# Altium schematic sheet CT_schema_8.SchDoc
size 277 x 170 mm
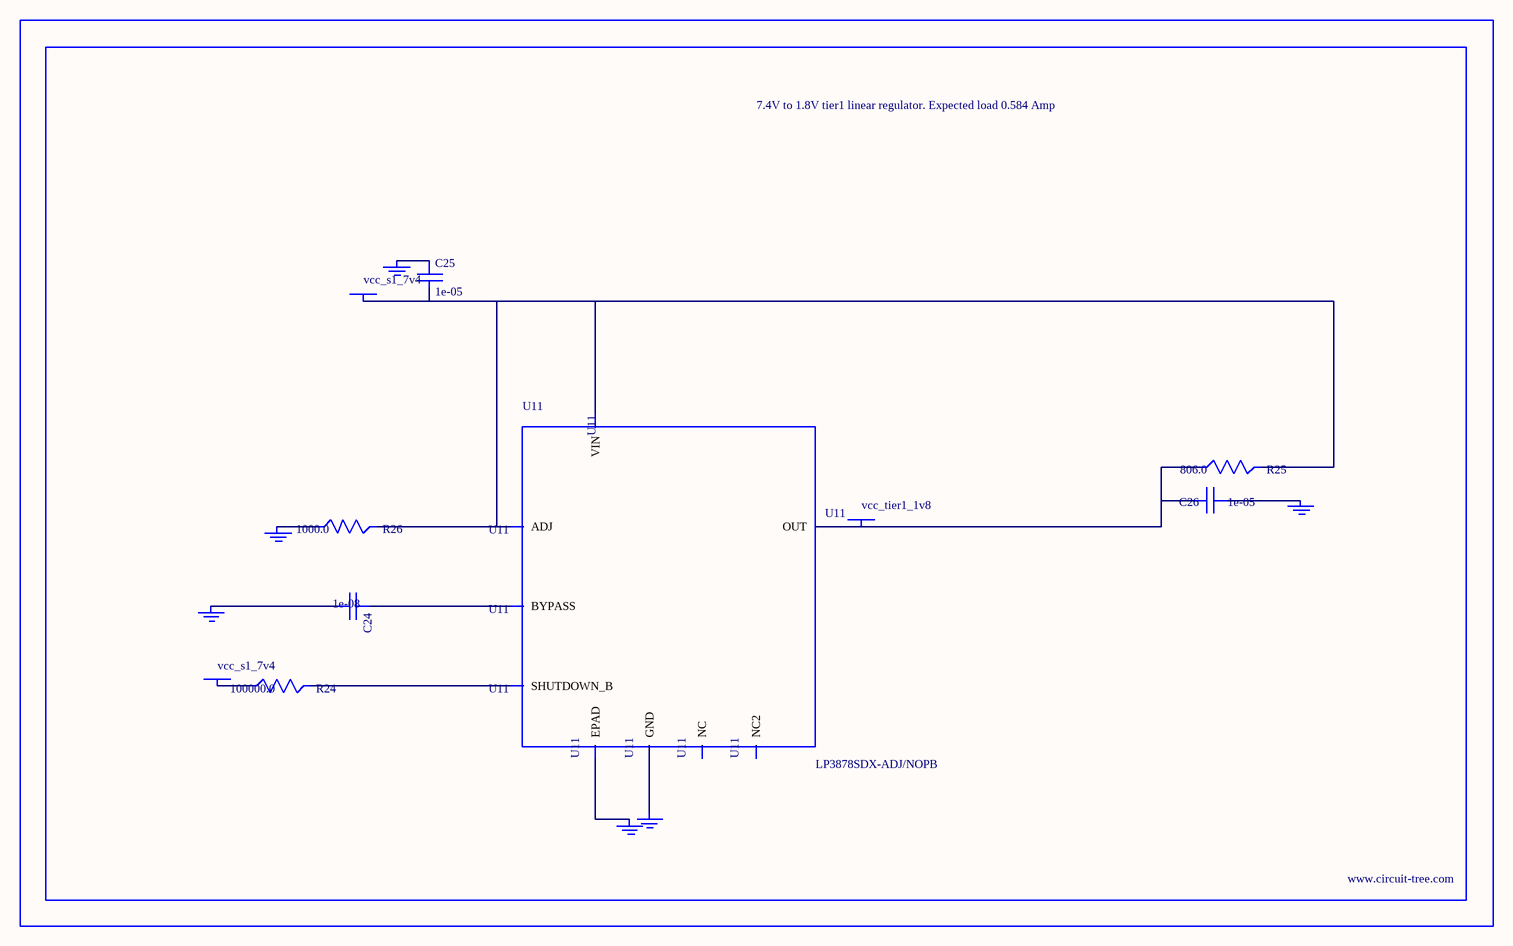
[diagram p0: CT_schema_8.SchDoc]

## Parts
BORDER7  (no value)
C24  1e-08  [C0402]
C25  1e-05  [C1206]
C26  1e-05  [C0805]
GND_INSTANCE_7_0  (no value)
GND_INSTANCE_7_1  (no value)
GND_INSTANCE_7_2  (no value)
GND_INSTANCE_7_3  (no value)
GND_INSTANCE_7_4  (no value)
GND_INSTANCE_7_5  (no value)
POWER_INSTANCE_7_0  vcc_s1_7v4
POWER_INSTANCE_7_1  vcc_s1_7v4
POWER_INSTANCE_7_2  vcc_tier1_1v8
R24  100000.0  [R0603]
R25  806.0  [R0603]
R26  1000.0  [R0603]
U11  LP3878SDX-ADJ/NOPB  [WSON-8]

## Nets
NetC24_1: C24.1 U11.1(BYPASS)
NetC24_2: C24.2 GND_INSTANCE_7_0.0(GND)
NetC25_1: C25.1 GND_INSTANCE_7_1.0(GND)
NetC25_2: C25.2 POWER_INSTANCE_7_0.0(PWR) R25.2 R26.2 U11.4(VIN) U11.6(ADJ)
NetC26_1: C26.1 GND_INSTANCE_7_2.0(GND)
NetC26_2: C26.2 POWER_INSTANCE_7_2.0(PWR) R25.1 U11.5(OUT)
NetGND_INSTANCE_7_3_0: GND_INSTANCE_7_3.0(GND) R26.1
NetGND_INSTANCE_7_4_0: GND_INSTANCE_7_4.0(GND) U11.PAD(EPAD)
NetGND_INSTANCE_7_5_0: GND_INSTANCE_7_5.0(GND) U11.3(GND)
NetPOWER_INSTANCE_7_1_0: POWER_INSTANCE_7_1.0(PWR) R24.1
NetR24_2: R24.2 U11.8(SHUTDOWN_B)

Not connected (* = marked no-connect by the designer): U11 2(NC) 7(NC2)

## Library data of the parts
BORDER7 = BORDER_PAGE7
C24 = C0402C103K3RAC
C25 = C1206C106K3RACTU
C26 = GRM219R60J106ME19D
GND_INSTANCE_7_0-GND_INSTANCE_7_5 = GND
POWER_INSTANCE_7_0-POWER_INSTANCE_7_2 = PWR
R24 = RC0603JR-07100KL
R25 = ERJ-3EKF8060V
R26 = RC0603JR-071KL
